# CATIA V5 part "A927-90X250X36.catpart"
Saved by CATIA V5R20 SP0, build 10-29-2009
Part number: A927-90X250X36
Source: Unknown
Property "A": "50.000"
Property "ARTICLENO": "A927-90X250X36"
Property "BOMINFO": "A927-90X250X36"
Property "CODE": "A927-90X250X36"
Property "CREATOR": "CADENAS GmbH"
Property "D": "18.000"
Property "D1": "26.000"
Property "F": "28.000"
Property "FORM": "A"
Property "L": "250.000"
Property "L1": "100.000"
Property "L2": "20.000"
Property "L3": "50.000"
Property "LINA": "A927-90X250X36"
Property "NB": "A927-90X250X36"
Property "NBSYN": "$CODE."
Property "NN": "A927"
Property "NT": "VDI 3387 Removable Die Heels, steel and self-lubricating"
Property "R": "25.000"
Property "S": "36.000"
Property "SUPPLIER": "CF"
Property "T": "21.000"
Property "W": "90.000"
Bounding box of the stored display mesh (mm): x -45 to 45, y 0 to 250, z -36 to 0
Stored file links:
  C:\Users\borellobunino\Desktop\3D X SITO CF\A927\GSB_OILLESS_G2290509025036\CATIAV5\A927-90X250X36.catpart
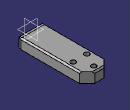
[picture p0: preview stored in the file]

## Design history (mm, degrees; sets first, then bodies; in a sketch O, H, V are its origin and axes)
Body1 "Geometry.1" (main body)
  Solid1 "A927-90X250X36.catpart": solid without history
